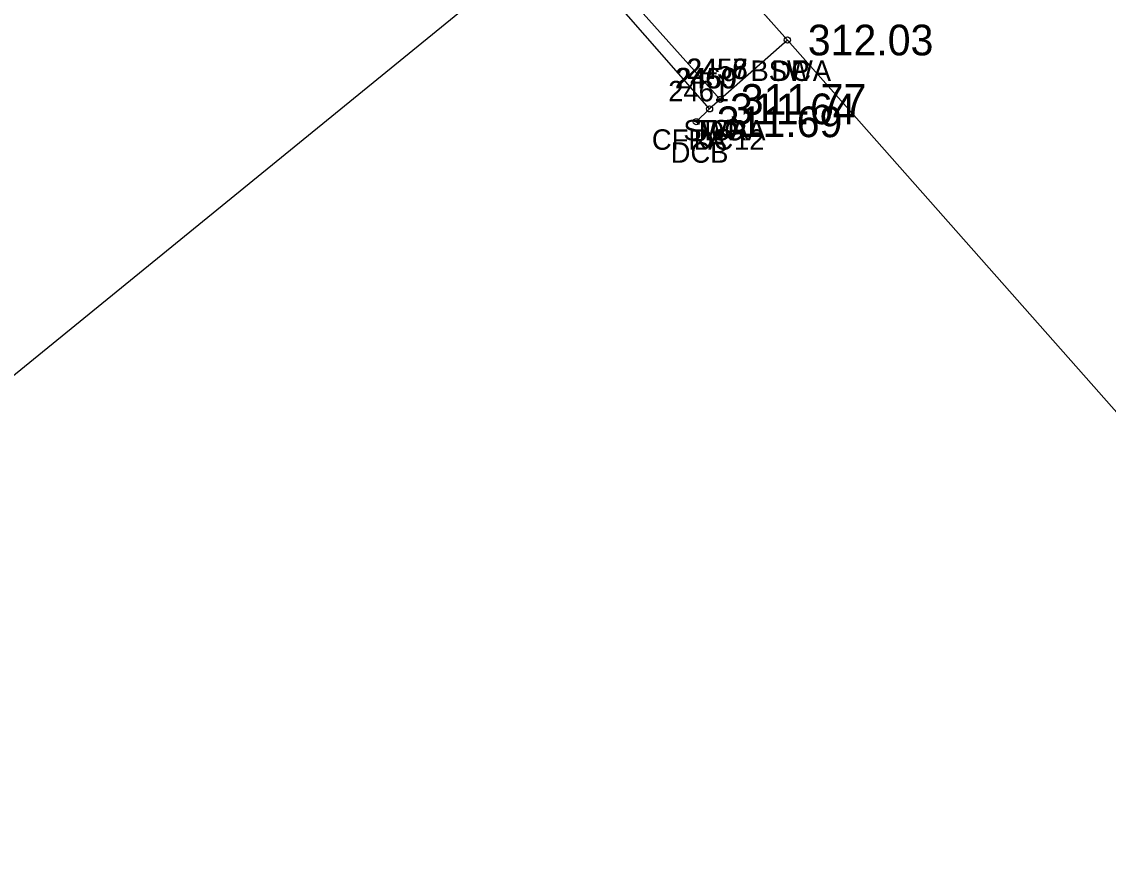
# Model space of a CAD drawing. Extents: x 1970076 to 1971136, y 803126 to 804215.
# Drawn here: x 1970411.6 to 1970464.7, y 803757.2 to 803798.1 of the extents above; entities that cross this region are included whole.
import ezdxf

# ---------------------------------------------------------------- set-up
doc = ezdxf.new("R2010")
doc.units = 0
for name, color, linetype in [('RD_EX_Conc', 7, 'Continuous'), ('RD_EX_Conc_txCode', 7, 'Continuous'), ('RD_EX_DR_Pipe', 7, 'Continuous'), ('RD_EX_Driveway', 7, 'Continuous'), ('RD_EX_Driveway_txCode', 7, 'Continuous'), ('RD_EX_TX_Conc_ELEV', 7, 'Continuous'), ('RD_EX_TX_Driveway_ELEV', 7, 'Continuous'), ('RD_SMD_Locator', 7, 'Continuous')]:
    doc.layers.add(name, color=color, linetype=linetype)

msp = doc.modelspace()

# ---------------------------------------------------------------- linework, layer by layer
at = {"layer": 'RD_EX_Conc'}
for p, q in [((1970449.054, 803797.204), (1970439.8, 803807.608)), ((1970445.779, 803794.298), (1970436.328, 803804.835)), ((1970445.254, 803793.84), (1970435.971, 803804.426))]:
    msp.add_line(p, q, dxfattribs=at)
msp.add_lwpolyline([(1970471.067, 803763.404), (1970471.769, 803764.011), (1970472.273, 803764.439), (1970475.485, 803767.3), (1970449.054, 803797.204), (1970445.779, 803794.298), (1970445.254, 803793.84), (1970444.605, 803793.207)], dxfattribs=at)
at = {"layer": 'RD_EX_DR_Pipe'}
msp.add_line((1970391.537, 803764.762), (1970446.305, 803809.387), dxfattribs=at)
at = {"layer": 'RD_EX_Driveway'}
msp.add_lwpolyline([(1970484.204, 803757.166), (1970475.485, 803767.3), (1970449.054, 803797.204), (1970439.8, 803807.608), (1970418.954, 803831.275), (1970412.581, 803837.881)], dxfattribs=at)
at = {"layer": 'RD_SMD_Locator'}
for centre in [(1970449.054, 803797.204), (1970449.054, 803797.204), (1970449.054, 803797.204), (1970445.779, 803794.298), (1970445.779, 803794.298), (1970445.779, 803794.298), (1970445.254, 803793.84), (1970445.254, 803793.84), (1970444.605, 803793.207)]:
    msp.add_circle(centre, 0.15, dxfattribs=at)

# ---------------------------------------------------------------- texts
at = {"layer": 'RD_EX_Conc_txCode'}
for s, p in [('2456', (1970444.125, 803795.298)), ('2457', (1970444.149, 803795.298)), ('2458', (1970444.149, 803795.298)), ('2460', (1970443.561, 803794.84)), ('2459', (1970443.624, 803794.84)), ('BSWA', (1970447.251, 803795.204)), ('DC', (1970448.275, 803795.204)), ('2461', (1970443.235, 803794.207)), ('SWRA', (1970443.976, 803792.298)), ('TCA', (1970444.495, 803792.298)), ('DC', (1970444.999, 803792.298)), ('CFRA 12', (1970442.435, 803791.84)), ('DC', (1970444.474, 803791.84)), ('DCB', (1970443.353, 803791.207))]:
    msp.add_text(s, height=1, dxfattribs=at).set_placement(p)
at = {"layer": 'RD_EX_Driveway_txCode'}
msp.add_text('DP', height=1, dxfattribs=at).set_placement((1970448.275, 803795.204))
at = {"layer": 'RD_EX_TX_Conc_ELEV'}
for s, p in [('312.03', (1970450.054, 803796.454)), ('312.03', (1970450.054, 803796.454)), ('311.77', (1970446.779, 803793.548)), ('311.77', (1970446.779, 803793.548)), ('311.77', (1970446.779, 803793.548)), ('311.64', (1970446.254, 803793.09)), ('311.64', (1970446.254, 803793.09)), ('311.69', (1970445.605, 803792.457))]:
    msp.add_text(s, height=1.5, dxfattribs=at).set_placement(p)
at = {"layer": 'RD_EX_TX_Driveway_ELEV'}
msp.add_text('312.03', height=1.5, dxfattribs=at).set_placement((1970450.054, 803796.454))

doc.saveas('drawing.dxf')
